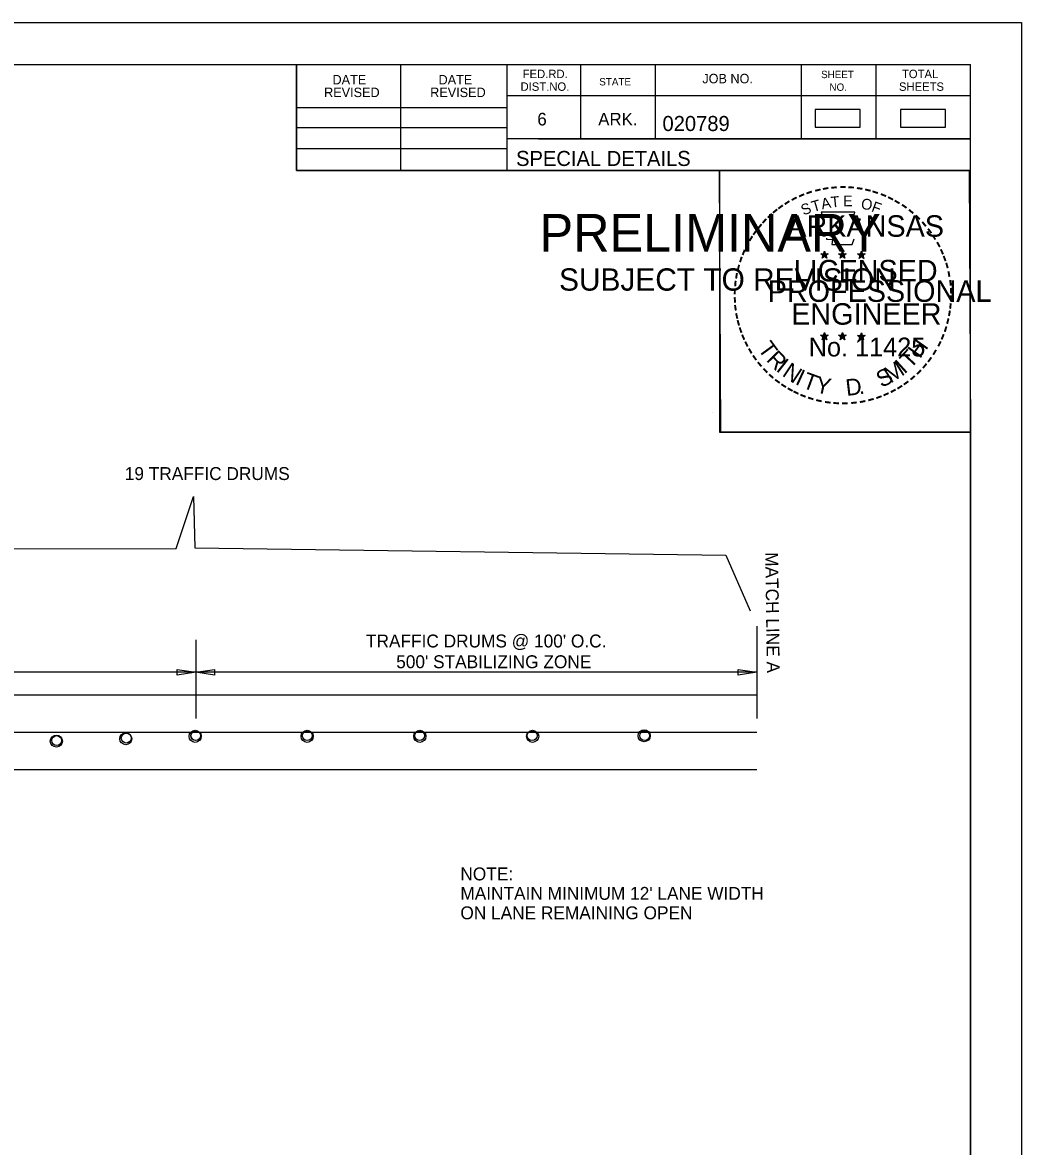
# Model space of a CAD drawing. Extents: x 1374897 to 1375063, y 381144 to 381251.
# Drawn here: x 1375016.8 to 1375063.2, y 381198.7 to 381251 of the extents above; entities that cross this region are included whole.
import ezdxf

# ---------------------------------------------------------------- set-up
doc = ezdxf.new("R2010")
doc.units = 0
for name, color, linetype in [('Default', 7, 'Continuous'), ('R_Border', 7, 'Continuous'), ('R_Border PE', 7, 'Continuous'), ('R_Border Prem', 7, 'Continuous'), ('R_No Plot', 7, 'Continuous')]:
    doc.layers.add(name, color=color, linetype=linetype)

msp = doc.modelspace()

# ---------------------------------------------------------------- linework, layer by layer
at = {"layer": 'Default'}
for p, q in [((1375050.934, 381222.892), (1375050.934, 381218.587)), ((1375024.856, 381222.244), (1375024.856, 381218.587)), ((1375024.856, 381220.74), (1374979.655, 381220.74)), ((1375023.987, 381220.609), (1375023.987, 381220.87)), ((1375023.987, 381220.87), (1375024.856, 381220.74)), ((1375024.856, 381220.74), (1375023.987, 381220.609)), ((1375024.856, 381220.74), (1375025.726, 381220.87)), ((1375050.934, 381220.74), (1375024.856, 381220.74)), ((1375025.726, 381220.609), (1375024.856, 381220.74)), ((1375025.726, 381220.87), (1375025.726, 381220.609)), ((1375050.065, 381220.609), (1375050.065, 381220.87)), ((1375050.065, 381220.87), (1375050.934, 381220.74)), ((1375050.934, 381220.74), (1375050.065, 381220.609)), ((1374979.655, 381219.7), (1375050.934, 381219.7)), ((1374979.655, 381217.961), (1375050.934, 381217.961)), ((1374979.655, 381216.223), (1375050.934, 381216.223))]:
    msp.add_line(p, q, dxfattribs=at)
for points in [[(1375053.655, 381246.084), (1375055.738, 381246.084), (1375055.738, 381246.909), (1375053.655, 381246.909)], [(1375057.622, 381246.084), (1375059.705, 381246.084), (1375059.705, 381246.909), (1375057.622, 381246.909)]]:
    msp.add_lwpolyline(points, close=True, dxfattribs=at)
msp.add_lwpolyline([(1374980.142, 381223.824), (1374982.117, 381226.442), (1375023.943, 381226.49), (1375024.749, 381228.909), (1375024.822, 381226.525), (1375049.49, 381226.192), (1375050.632, 381223.594)], dxfattribs=at)
for centre, radius in [((1375045.704, 381217.79), 0.281), ((1375018.378, 381217.542), 0.281), ((1375018.39, 381217.566), 0.229), ((1375021.603, 381217.653), 0.281), ((1375021.626, 381217.681), 0.229), ((1375024.828, 381217.764), 0.281), ((1375024.851, 381217.797), 0.229), ((1375024.863, 381217.796), 0.229), ((1375030.033, 381217.764), 0.281), ((1375030.04, 381217.794), 0.229), ((1375035.275, 381217.764), 0.281), ((1375035.267, 381217.794), 0.229), ((1375040.517, 381217.764), 0.281), ((1375040.494, 381217.794), 0.229), ((1375045.721, 381217.794), 0.229)]:
    msp.add_circle(centre, radius, dxfattribs=at)
at = {"layer": 'R_Border'}
for p, q in [((1374902.775, 381249.01), (1375060.865, 381249.01)), ((1375029.545, 381244.07), (1375029.545, 381249.01)), ((1375034.385, 381244.07), (1375034.385, 381249.01)), ((1375039.315, 381249.01), (1375039.315, 381244.07)), ((1375042.735, 381249.01), (1375042.735, 381245.54)), ((1375046.205, 381249.01), (1375046.205, 381245.54)), ((1375052.995, 381249.01), (1375052.995, 381245.54)), ((1375056.465, 381249.01), (1375056.465, 381245.54)), ((1375060.865, 381146.28), (1375060.865, 381249.01)), ((1375060.865, 381247.54), (1375039.315, 381247.54)), ((1375060.865, 381247.55), (1375060.865, 381247.55)), ((1375029.545, 381247), (1375039.315, 381247)), ((1375029.545, 381246.07), (1375039.315, 381246.07)), ((1375060.865, 381245.54), (1375039.315, 381245.54)), ((1375040.795, 381245.54), (1375060.865, 381245.54)), ((1375029.545, 381245.1), (1375039.315, 381245.1)), ((1375060.865, 381244.07), (1375029.545, 381244.07))]:
    msp.add_line(p, q, dxfattribs=at)
at = {"layer": 'R_Border PE'}
for p, q in [((1375053.907, 381240.198), (1375054.082, 381240.142)), ((1375053.907, 381240.198), (1375054.034, 381240.175)), ((1375053.907, 381240.198), (1375054.026, 381240.137)), ((1375053.974, 381239.994), (1375054.082, 381240.142)), ((1375053.974, 381239.994), (1375054.037, 381240.116)), ((1375053.974, 381239.994), (1375054.081, 381240.102)), ((1375054.082, 381240.325), (1375054.061, 381240.199)), ((1375054.188, 381239.994), (1375054.081, 381240.101)), ((1375054.082, 381240.142), (1375054.082, 381240.325)), ((1375054.082, 381240.325), (1375054.106, 381240.2)), ((1375054.255, 381240.198), (1375054.082, 381240.142)), ((1375054.188, 381239.994), (1375054.082, 381240.142)), ((1375054.255, 381240.198), (1375054.112, 381240.173)), ((1375054.188, 381239.994), (1375054.12, 381240.139)), ((1375054.255, 381240.198), (1375054.153, 381240.147)), ((1375054.742, 381240.198), (1375054.917, 381240.142)), ((1375054.742, 381240.198), (1375054.869, 381240.175)), ((1375054.742, 381240.198), (1375054.861, 381240.137)), ((1375054.809, 381239.994), (1375054.917, 381240.142)), ((1375054.809, 381239.994), (1375054.872, 381240.116)), ((1375054.809, 381239.994), (1375054.916, 381240.102)), ((1375054.917, 381240.325), (1375054.896, 381240.199)), ((1375055.023, 381239.994), (1375054.916, 381240.101)), ((1375054.917, 381240.142), (1375054.917, 381240.325)), ((1375054.917, 381240.325), (1375054.941, 381240.2)), ((1375055.09, 381240.198), (1375054.917, 381240.142)), ((1375055.023, 381239.994), (1375054.917, 381240.142)), ((1375055.09, 381240.198), (1375054.947, 381240.173)), ((1375055.023, 381239.994), (1375054.955, 381240.139)), ((1375055.09, 381240.198), (1375054.988, 381240.147)), ((1375055.624, 381240.192), (1375055.799, 381240.136)), ((1375055.624, 381240.192), (1375055.751, 381240.169)), ((1375055.624, 381240.192), (1375055.743, 381240.131)), ((1375055.691, 381239.988), (1375055.799, 381240.136)), ((1375055.691, 381239.988), (1375055.754, 381240.11)), ((1375055.691, 381239.988), (1375055.798, 381240.096)), ((1375055.799, 381240.319), (1375055.778, 381240.193)), ((1375055.905, 381239.988), (1375055.798, 381240.095)), ((1375055.799, 381240.136), (1375055.799, 381240.319)), ((1375055.799, 381240.319), (1375055.823, 381240.194)), ((1375055.972, 381240.192), (1375055.799, 381240.136)), ((1375055.905, 381239.988), (1375055.799, 381240.136)), ((1375055.972, 381240.192), (1375055.829, 381240.167)), ((1375055.905, 381239.988), (1375055.837, 381240.133)), ((1375055.972, 381240.192), (1375055.87, 381240.141)), ((1375053.905, 381236.411), (1375054.08, 381236.356)), ((1375053.905, 381236.411), (1375054.032, 381236.389)), ((1375053.905, 381236.411), (1375054.024, 381236.35)), ((1375053.972, 381236.207), (1375054.08, 381236.356)), ((1375054.08, 381236.538), (1375054.059, 381236.412)), ((1375054.08, 381236.356), (1375054.08, 381236.538)), ((1375054.08, 381236.538), (1375054.104, 381236.413)), ((1375054.253, 381236.411), (1375054.08, 381236.356)), ((1375054.186, 381236.207), (1375054.08, 381236.356)), ((1375054.253, 381236.411), (1375054.11, 381236.387)), ((1375054.186, 381236.207), (1375054.118, 381236.353)), ((1375054.253, 381236.411), (1375054.151, 381236.36)), ((1375054.74, 381236.411), (1375054.914, 381236.356)), ((1375054.74, 381236.411), (1375054.866, 381236.389)), ((1375054.74, 381236.411), (1375054.858, 381236.35)), ((1375054.806, 381236.207), (1375054.914, 381236.356)), ((1375054.914, 381236.538), (1375054.894, 381236.412)), ((1375054.914, 381236.356), (1375054.914, 381236.538)), ((1375054.914, 381236.538), (1375054.939, 381236.413)), ((1375055.088, 381236.411), (1375054.914, 381236.356)), ((1375055.021, 381236.207), (1375054.914, 381236.356)), ((1375055.088, 381236.411), (1375054.945, 381236.387)), ((1375055.021, 381236.207), (1375054.952, 381236.353)), ((1375055.088, 381236.411), (1375054.986, 381236.36)), ((1375055.623, 381236.406), (1375055.798, 381236.351)), ((1375055.623, 381236.406), (1375055.75, 381236.384)), ((1375055.623, 381236.406), (1375055.742, 381236.345)), ((1375055.69, 381236.202), (1375055.798, 381236.351)), ((1375055.798, 381236.533), (1375055.777, 381236.407)), ((1375055.798, 381236.351), (1375055.798, 381236.533)), ((1375055.798, 381236.533), (1375055.822, 381236.408)), ((1375055.971, 381236.406), (1375055.798, 381236.351)), ((1375055.904, 381236.202), (1375055.798, 381236.351)), ((1375055.971, 381236.406), (1375055.828, 381236.382)), ((1375055.904, 381236.202), (1375055.836, 381236.348)), ((1375055.971, 381236.406), (1375055.869, 381236.355)), ((1375053.972, 381236.207), (1375054.035, 381236.329)), ((1375053.972, 381236.207), (1375054.079, 381236.316)), ((1375054.186, 381236.207), (1375054.079, 381236.314)), ((1375054.806, 381236.207), (1375054.869, 381236.329)), ((1375054.806, 381236.207), (1375054.913, 381236.316)), ((1375055.021, 381236.207), (1375054.913, 381236.314)), ((1375055.69, 381236.202), (1375055.753, 381236.324)), ((1375055.69, 381236.202), (1375055.797, 381236.311)), ((1375055.904, 381236.202), (1375055.797, 381236.309))]:
    msp.add_line(p, q, dxfattribs=at)
for points in [[(1375053.928, 381242.137), (1375054.062, 381241.723)], [(1375055.683, 381241.676), (1375055.754, 381241.818), (1375055.412, 381241.806), (1375055.486, 381242.137), (1375053.928, 381242.137)], [(1375054.174, 381240.925), (1375054.174, 381240.882), (1375054.455, 381240.872), (1375054.428, 381240.636), (1375055.363, 381240.636), (1375055.464, 381240.904)], [(1375054.082, 381240.325), (1375054.188, 381239.994), (1375053.907, 381240.198), (1375054.255, 381240.198), (1375053.974, 381239.994), (1375054.082, 381240.325)], [(1375054.917, 381240.325), (1375055.023, 381239.994), (1375054.742, 381240.198), (1375055.09, 381240.198), (1375054.809, 381239.994), (1375054.917, 381240.325)], [(1375055.799, 381240.319), (1375055.905, 381239.988), (1375055.624, 381240.192), (1375055.972, 381240.192), (1375055.691, 381239.988), (1375055.799, 381240.319)], [(1375054.08, 381236.538), (1375054.186, 381236.207), (1375053.905, 381236.411), (1375054.253, 381236.411), (1375053.972, 381236.207), (1375054.08, 381236.538)], [(1375054.914, 381236.538), (1375055.021, 381236.207), (1375054.74, 381236.411), (1375055.088, 381236.411), (1375054.806, 381236.207), (1375054.914, 381236.538)], [(1375055.798, 381236.533), (1375055.904, 381236.202), (1375055.623, 381236.406), (1375055.971, 381236.406), (1375055.69, 381236.202), (1375055.798, 381236.533)]]:
    msp.add_lwpolyline(points, dxfattribs=at)
for centre, radius in [((1375054.081, 381240.142), 0.0861), ((1375054.081, 381240.142), 0.0723), ((1375054.081, 381240.142), 0.0579), ((1375054.081, 381240.142), 0.0495), ((1375054.081, 381240.142), 0.0374), ((1375054.081, 381240.142), 0.0248), ((1375054.081, 381240.142), 0.0148), ((1375054.916, 381240.142), 0.0861), ((1375054.916, 381240.142), 0.0723), ((1375054.916, 381240.142), 0.0579), ((1375054.916, 381240.142), 0.0495), ((1375054.916, 381240.142), 0.0374), ((1375054.916, 381240.142), 0.0248), ((1375054.916, 381240.142), 0.0148), ((1375055.798, 381240.136), 0.0861), ((1375055.798, 381240.136), 0.0723), ((1375055.798, 381240.136), 0.0579), ((1375055.798, 381240.136), 0.0495), ((1375055.798, 381240.136), 0.0374), ((1375055.798, 381240.136), 0.0248), ((1375055.798, 381240.136), 0.0148), ((1375054.079, 381236.355), 0.0861), ((1375054.079, 381236.355), 0.0723), ((1375054.079, 381236.355), 0.0579), ((1375054.079, 381236.355), 0.0495), ((1375054.079, 381236.355), 0.0374), ((1375054.079, 381236.355), 0.0248), ((1375054.079, 381236.355), 0.0148), ((1375054.914, 381236.355), 0.0861), ((1375054.914, 381236.355), 0.0723), ((1375054.914, 381236.355), 0.0579), ((1375054.914, 381236.355), 0.0495), ((1375054.914, 381236.355), 0.0374), ((1375054.914, 381236.355), 0.0248), ((1375054.914, 381236.355), 0.0148), ((1375055.797, 381236.35), 0.0861), ((1375055.797, 381236.35), 0.0723), ((1375055.797, 381236.35), 0.0579), ((1375055.797, 381236.35), 0.0495), ((1375055.797, 381236.35), 0.0374), ((1375055.797, 381236.35), 0.0248), ((1375055.797, 381236.35), 0.0148)]:
    msp.add_circle(centre, radius, dxfattribs=at)
at = {"layer": 'R_No Plot'}
for p, q in [((1374896.575, 381250.958), (1375063.241, 381250.958)), ((1375048.882, 381232.842), (1375048.882, 381232.842))]:
    msp.add_line(p, q, dxfattribs=at)
for points in [[(1374896.571, 381250.958), (1375063.241, 381250.958), (1375063.241, 381144.289), (1374896.571, 381144.289)], [(1375019.735, 381249.01), (1375029.545, 381249.01), (1375029.545, 381244.07), (1375037.601, 381244.07), (1375049.201, 381244.07), (1375049.201, 381231.904), (1375060.865, 381231.904), (1375060.865, 381146.28), (1374902.775, 381146.28), (1374902.775, 381249.01)], [(1375049.201, 381244.07), (1375060.805, 381244.07), (1375060.865, 381231.904), (1375049.261, 381231.904)]]:
    msp.add_lwpolyline(points, close=True, dxfattribs=at)

# ---------------------------------------------------------------- texts
at = {"layer": 'Default'}
for s, p in [('19 TRAFFIC DRUMS', (1375021.558, 381229.681)), ("TRAFFIC DRUMS @ 100' O.C.", (1375032.77, 381221.896)), ("500' STABILIZING ZONE", (1375034.175, 381220.932)), ('NOTE:', (1375037.158, 381211.066)), ("MAINTAIN MINIMUM 12' LANE WIDTH", (1375037.158, 381210.161)), ('ON LANE REMAINING OPEN', (1375037.158, 381209.256))]:
    msp.add_text(s, height=0.6, dxfattribs=at).set_placement(p)
msp.add_text('MATCH LINE A', height=0.6, rotation=270.8059, dxfattribs=at).set_placement((1375051.326, 381226.321))
at = {"layer": 'R_Border'}
for s, height, p in [('DATE', 0.4396, (1375031.214, 381248.078)), ('DATE', 0.4396, (1375036.144, 381248.078)), ('FED.RD.', 0.391, (1375040.055, 381248.37)), ('STATE', 0.342, (1375043.615, 381248.03)), ('JOB NO.', 0.4396, (1375048.405, 381248.13)), ('SHEET', 0.342, (1375053.925, 381248.37)), ('TOTAL', 0.391, (1375057.685, 381248.37)), ('REVISED', 0.4396, (1375030.824, 381247.488)), ('REVISED', 0.4396, (1375035.754, 381247.488)), ('DIST.NO.', 0.391, (1375039.955, 381247.78)), ('NO.', 0.342, (1375054.315, 381247.78)), ('SHEETS', 0.391, (1375057.545, 381247.78)), ('6', 0.586, (1375040.735, 381246.17)), ('ARK.', 0.5861, (1375043.565, 381246.17)), ('020789', 0.7, (1375046.553, 381245.91)), ('SPECIAL DETAILS', 0.7, (1375039.747, 381244.285))]:
    msp.add_text(s, height=height, dxfattribs=at).set_placement(p)
at = {"layer": 'R_Border PE'}
for s, height, rotation, p in [('-', 0.8, 19.1761, (1375053.302, 381242.7)), ('-', 0.8, 13.6302, (1375053.677, 381242.821)), ('-', 0.8, 10.2193, (1375054.016, 381242.902)), ('-', 0.8, 5.8968, (1375054.38, 381242.957)), ('-', 0.8, 0.1862, (1375054.766, 381242.993)), ('-', 0.8, 357.743, (1375055.128, 381242.986)), ('-', 0.8, 352.1617, (1375055.5, 381242.958)), ('-', 0.8, 347.2049, (1375055.859, 381242.901)), ('-', 0.8, 342.3362, (1375056.177, 381242.824)), ('-', 0.8, 34.0636, (1375052.37, 381242.222)), ('-', 0.8, 28.7918, (1375052.668, 381242.407)), ('-', 0.8, 24.3072, (1375052.985, 381242.566)), ('T', 0.5, 16.4036, (1375053.562, 381242.141)), ('A', 0.5, 11.2132, (1375053.975, 381242.267)), ('T', 0.5, 6.0228, (1375054.4, 381242.35)), ('E', 0.5, 0.8323, (1375054.952, 381242.405)), ('O', 0.5, 350.4515, (1375055.754, 381242.3)), ('F', 0.5, 340.0707, (1375056.231, 381242.186)), ('-', 0.8, 337.8551, (1375056.544, 381242.712)), ('-', 0.8, 334.1211, (1375056.86, 381242.577)), ('-', 0.8, 329.6409, (1375057.149, 381242.435)), ('-', 0.8, 42.9622, (1375051.626, 381241.627)), ('-', 0.8, 38.9507, (1375051.843, 381241.836)), ('-', 0.8, 36.2317, (1375052.081, 381242.025)), ('S', 0.5, 21.594, (1375053.105, 381241.976)), ('-', 0.8, 325.8627, (1375057.471, 381242.255)), ('-', 0.8, 320.5297, (1375057.776, 381242.042)), ('-', 0.8, 50.6142, (1375051.201, 381241.145)), ('-', 0.8, 48.4231, (1375051.402, 381241.388)), ('-', 0.8, 315.5786, (1375058.075, 381241.798)), ('-', 0.8, 309.8797, (1375058.36, 381241.523)), ('-', 0.8, 58.0706, (1375050.832, 381240.598)), ('-', 0.8, 54.2325, (1375050.994, 381240.862)), ('-', 0.8, 306.6522, (1375058.622, 381241.222)), ('-', 0.7, 303.6753, (1375058.865, 381240.938)), ('-', 0.8, 62.8713, (1375050.675, 381240.291)), ('-', 0.8, 299.6684, (1375059.025, 381240.634)), ('-', 0.8, 72.3945, (1375050.436, 381239.671)), ('-', 0.8, 67.7743, (1375050.546, 381239.986)), ('-', 0.8, 294.6628, (1375059.187, 381240.328)), ('-', 0.8, 290.5728, (1375059.315, 381240.04)), ('-', 0.8, 75.461, (1375050.338, 381239.314)), ('-', 0.8, 285.1233, (1375059.432, 381239.75)), ('-', 0.8, 81.2013, (1375050.272, 381238.957)), ('-', 0.8, 280.5493, (1375059.532, 381239.379)), ('-', 0.8, 276.5962, (1375059.613, 381238.995)), ('-', 0.8, 89.0622, (1375050.221, 381238.261)), ('-', 0.8, 85.1863, (1375050.234, 381238.612)), ('-', 0.8, 274.3301, (1375059.643, 381238.634)), ('-', 0.8, 94.1959, (1375050.239, 381237.899)), ('-', 0.8, 269.9407, (1375059.66, 381238.318)), ('-', 0.8, 98.9479, (1375050.275, 381237.565)), ('-', 0.8, 101.7149, (1375050.342, 381237.199)), ('-', 0.8, 260.9953, (1375059.615, 381237.658)), ('-', 0.8, 263.5172, (1375059.651, 381237.985)), ('-', 0.8, 105.4578, (1375050.423, 381236.901)), ('-', 0.8, 255.7626, (1375059.56, 381237.319)), ('-', 0.8, 109.0874, (1375050.531, 381236.586)), ('-', 0.8, 114.0643, (1375050.658, 381236.288)), ('-', 0.8, 247.8887, (1375059.358, 381236.622)), ('-', 0.8, 252.8681, (1375059.47, 381236.959)), ('-', 0.8, 115.7289, (1375050.81, 381235.979)), ('-', 0.8, 120.4471, (1375050.989, 381235.686)), ('T', 0.77, 306.0406, (1375050.96, 381235.775)), ('H', 0.77, 54.6088, (1375058.52, 381235.292)), ('-', 0.8, 244.6197, (1375059.227, 381236.308)), ('-', 0.8, 125.8934, (1375051.19, 381235.405)), ('R', 0.77, 314.005, (1375051.341, 381235.251)), ('I', 0.77, 321.9694, (1375051.791, 381234.785)), ('T', 0.77, 46.6444, (1375058.075, 381234.821)), ('-', 0.8, 233.8452, (1375058.829, 381235.605)), ('-', 0.8, 239.0712, (1375059.03, 381235.932)), ('-', 0.8, 130.7181, (1375051.421, 381235.129)), ('-', 0.8, 134.2238, (1375051.68, 381234.857)), ('N', 0.77, 326.5002, (1375052.075, 381234.549)), ('I', 0.77, 335.3603, (1375052.679, 381234.156)), ('S', 0.77, 26.9312, (1375056.733, 381233.956)), ('M', 0.77, 32.6563, (1375057.152, 381234.159)), ('I', 0.77, 42.1136, (1375057.794, 381234.582)), ('-', 0.8, 225.7653, (1375058.375, 381235.04)), ('-', 0.8, 231.2538, (1375058.614, 381235.322)), ('-', 0.8, 138.9338, (1375051.942, 381234.625)), ('-', 0.8, 144.6463, (1375052.22, 381234.422)), ('T', 0.77, 339.8912, (1375053.009, 381233.992)), ('Y', 0.77, 347.8556, (1375053.618, 381233.77)), ('D', 0.77, 6.3969, (1375055.11, 381233.591)), ('-', 0.8, 215.7363, (1375057.839, 381234.55)), ('-', 0.8, 221.0851, (1375058.114, 381234.786)), ('-', 0.8, 148.0898, (1375052.501, 381234.236)), ('-', 0.8, 151.5704, (1375052.79, 381234.074)), ('-', 0.8, 154.6002, (1375053.051, 381233.95)), ('.', 0.77, 13.7642, (1375055.706, 381233.654)), ('-', 0.8, 204.2516, (1375056.981, 381234.024)), ('-', 0.8, 207.3568, (1375057.293, 381234.183)), ('-', 0.8, 212.2491, (1375057.572, 381234.356)), ('-', 0.8, 158.5612, (1375053.363, 381233.823)), ('-', 0.8, 162.7983, (1375053.707, 381233.717)), ('-', 0.8, 167.5555, (1375054.064, 381233.635)), ('-', 0.8, 173.1155, (1375054.45, 381233.58)), ('-', 0.8, 176.5183, (1375054.824, 381233.553)), ('-', 0.8, 181.5918, (1375055.196, 381233.563)), ('-', 0.8, 185.8167, (1375055.601, 381233.601)), ('-', 0.8, 191.2858, (1375055.969, 381233.667)), ('-', 0.8, 195.4743, (1375056.333, 381233.766)), ('-', 0.8, 200.7184, (1375056.672, 381233.887))]:
    msp.add_text(s, height=height, rotation=rotation, dxfattribs=at).set_placement(p)
for s, height, p in [('ARKANSAS', 1, (1375052.354, 381240.993)), ('DWB', 0.005, (1375054.076, 381240.14)), ('DWB', 0.005, (1375054.91, 381240.14)), ('DWB', 0.005, (1375055.793, 381240.134)), ('LICENSED', 1, (1375052.653, 381238.918)), ('PROFESSIONAL', 1, (1375051.441, 381237.966)), ('ENGINEER', 1, (1375052.535, 381236.904)), ('DWB', 0.005, (1375054.074, 381236.353)), ('DWB', 0.005, (1375054.908, 381236.353)), ('DWB', 0.005, (1375055.792, 381236.348)), ('No. 11425', 0.8785, (1375053.349, 381235.428))]:
    msp.add_text(s, height=height, dxfattribs=at).set_placement(p)
at = {"layer": 'R_Border Prem'}
for s, height, p in [('PRELIMINARY', 1.75, (1375040.841, 381240.302)), ('DWB', 0.005, (1375041.214, 381241.226)), ('SUBJECT TO REVISION', 1.03756, (1375041.745, 381238.487))]:
    msp.add_text(s, height=height, dxfattribs=at).set_placement(p)

doc.saveas('drawing.dxf')
